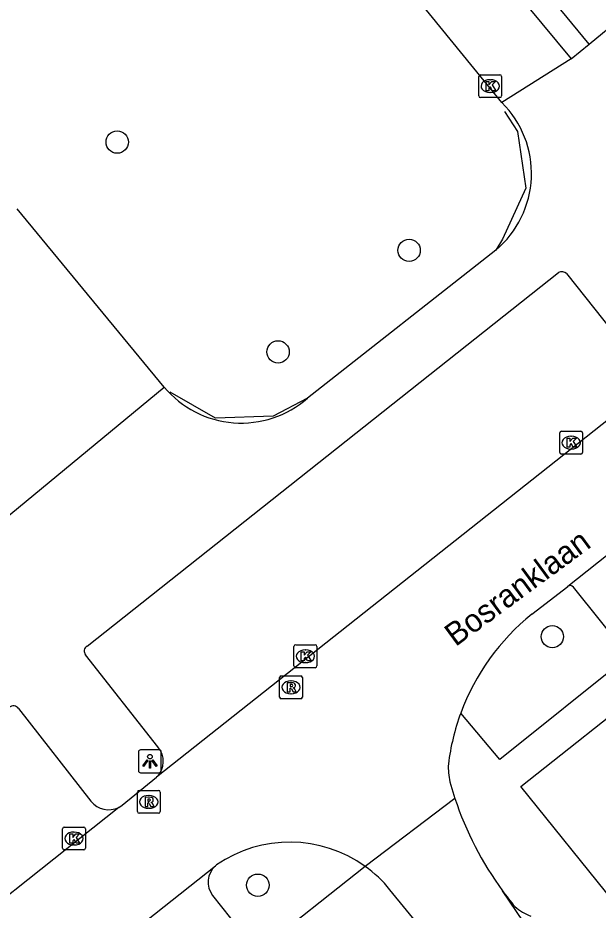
# Model space of a CAD drawing. Extents: x 162347 to 162868, y 381221 to 381813.
# Drawn here: x 162493.66 to 162519.02, y 381680.03 to 381719.03 of the extents above; entities that cross this region are included whole.
import ezdxf

# ---------------------------------------------------------------- set-up
doc = ezdxf.new("R2010")
doc.units = 0
for name, color, linetype in [('IMGEO_Boom', 7, 'Continuous'), ('IMGEO_Hek', 7, 'Continuous'), ('IMGEO_Kolk', 7, 'Continuous'), ('IMGEO_Lichtpunt', 7, 'Continuous'), ('IMGEO_Openbare_ruimte_label', 7, 'Continuous'), ('IMGEO_Pand', 7, 'Continuous'), ('IMGEO_Parkeervlak_open', 7, 'Continuous'), ('IMGEO_Rijbaan_lokaal_open', 7, 'Continuous'), ('IMGEO_Rioolput', 7, 'Continuous'), ('IMGEO_Voetpad_open', 7, 'Continuous')]:
    doc.layers.add(name, color=color, linetype=linetype)

msp = doc.modelspace()

# ---------------------------------------------------------------- linework, layer by layer
at = {"layer": 'IMGEO_Boom'}
for centre in [(162498.003, 381713.603), (162510.758, 381708.87), (162505.033, 381704.43), (162517.017, 381691.986), (162504.148, 381681.124)]:
    msp.add_circle(centre, 0.489, dxfattribs=at)
at = {"layer": 'IMGEO_Hek'}
for points in [[(162514.929, 381714.942), (162515.499, 381714.058), (162515.859, 381711.59), (162514.835, 381709.353), (162514.55, 381708.882)], [(162514.55, 381708.882), (162506.322, 381702.406)], [(162506.322, 381702.406), (162504.816, 381701.628), (162502.292, 381701.534), (162500.316, 381702.673)]]:
    msp.add_lwpolyline(points, dxfattribs=at)
at = {"layer": 'IMGEO_Kolk'}
for p, q in [((162513.802, 381715.621), (162513.802, 381716.473)), ((162513.877, 381716.547), (162514.729, 381716.547)), ((162514.803, 381716.473), (162514.803, 381715.621)), ((162514.29, 381716.327), (162514.315, 381716.327)), ((162514.313, 381715.767), (162514.288, 381715.767)), ((162514.729, 381715.547), (162513.877, 381715.547)), ((162517.34, 381700.036), (162517.34, 381700.888)), ((162517.415, 381700.962), (162518.267, 381700.962)), ((162518.341, 381700.888), (162518.341, 381700.036)), ((162517.828, 381700.742), (162517.853, 381700.742)), ((162517.851, 381700.182), (162517.826, 381700.182)), ((162518.267, 381699.962), (162517.415, 381699.962)), ((162505.727, 381690.704), (162505.727, 381691.556)), ((162505.802, 381691.63), (162506.654, 381691.63)), ((162506.728, 381691.556), (162506.728, 381690.704)), ((162506.215, 381691.41), (162506.24, 381691.41)), ((162506.238, 381690.85), (162506.213, 381690.85)), ((162506.654, 381690.63), (162505.802, 381690.63)), ((162495.615, 381682.738), (162495.615, 381683.59)), ((162495.69, 381683.664), (162496.542, 381683.664)), ((162496.103, 381683.444), (162496.128, 381683.444)), ((162496.616, 381683.59), (162496.616, 381682.738)), ((162496.542, 381682.664), (162495.69, 381682.664)), ((162496.126, 381682.884), (162496.101, 381682.884))]:
    msp.add_line(p, q, dxfattribs=at)
for points in [[(162513.802, 381715.621), (162513.802, 381716.473)], [(162513.877, 381716.547), (162514.729, 381716.547)], [(162514.803, 381716.473), (162514.803, 381715.621)], [(162514.123, 381716.247), (162514.246, 381716.247), (162514.246, 381716.096), (162514.376, 381716.247), (162514.54, 381716.247), (162514.394, 381716.096), (162514.547, 381715.847), (162514.395, 381715.847), (162514.31, 381716.011), (162514.246, 381715.944), (162514.246, 381715.847), (162514.123, 381715.847), (162514.123, 381716.247)], [(162514.729, 381715.547), (162513.877, 381715.547)], [(162517.34, 381700.036), (162517.34, 381700.888)], [(162517.415, 381700.962), (162518.267, 381700.962)], [(162518.341, 381700.888), (162518.341, 381700.036)], [(162517.661, 381700.662), (162517.784, 381700.662), (162517.784, 381700.511), (162517.914, 381700.662), (162518.078, 381700.662), (162517.932, 381700.511), (162518.085, 381700.262), (162517.933, 381700.262), (162517.848, 381700.426), (162517.784, 381700.359), (162517.784, 381700.262), (162517.661, 381700.262), (162517.661, 381700.662)], [(162518.267, 381699.962), (162517.415, 381699.962)], [(162505.727, 381690.704), (162505.727, 381691.556)], [(162505.802, 381691.63), (162506.654, 381691.63)], [(162506.728, 381691.556), (162506.728, 381690.704)], [(162506.048, 381691.33), (162506.171, 381691.33), (162506.171, 381691.179), (162506.301, 381691.33), (162506.465, 381691.33), (162506.319, 381691.179), (162506.472, 381690.93), (162506.32, 381690.93), (162506.235, 381691.094), (162506.171, 381691.027), (162506.171, 381690.93), (162506.048, 381690.93), (162506.048, 381691.33)], [(162506.654, 381690.63), (162505.802, 381690.63)], [(162495.615, 381682.738), (162495.615, 381683.59)], [(162495.69, 381683.664), (162496.542, 381683.664)], [(162495.936, 381683.364), (162496.059, 381683.364), (162496.059, 381683.213), (162496.189, 381683.364), (162496.353, 381683.364), (162496.207, 381683.213), (162496.36, 381682.964), (162496.208, 381682.964), (162496.123, 381683.128), (162496.059, 381683.061), (162496.059, 381682.964), (162495.936, 381682.964), (162495.936, 381683.364)], [(162496.616, 381683.59), (162496.616, 381682.738)], [(162496.542, 381682.664), (162495.69, 381682.664)]]:
    msp.add_lwpolyline(points, dxfattribs=at)
for centre, start, end in [((162513.879, 381716.471), 91.552, 178.448), ((162513.879, 381716.471), 91.552, 178.448), ((162514.727, 381716.471), 1.552, 88.448), ((162514.727, 381716.471), 1.552, 88.448), ((162513.879, 381715.623), 181.552, 268.448), ((162513.879, 381715.623), 181.552, 268.448), ((162514.727, 381715.623), 271.552, 358.448), ((162514.727, 381715.623), 271.552, 358.448), ((162517.417, 381700.886), 91.552, 178.448), ((162517.417, 381700.886), 91.552, 178.448), ((162518.265, 381700.886), 1.552, 88.448), ((162518.265, 381700.886), 1.552, 88.448), ((162517.417, 381700.038), 181.552, 268.448), ((162517.417, 381700.038), 181.552, 268.448), ((162518.265, 381700.038), 271.552, 358.448), ((162518.265, 381700.038), 271.552, 358.448), ((162505.804, 381691.554), 91.552, 178.448), ((162505.804, 381691.554), 91.552, 178.448), ((162506.652, 381691.554), 1.552, 88.448), ((162506.652, 381691.554), 1.552, 88.448), ((162505.804, 381690.706), 181.552, 268.448), ((162505.804, 381690.706), 181.552, 268.448), ((162506.652, 381690.706), 271.552, 358.448), ((162506.652, 381690.706), 271.552, 358.448), ((162495.692, 381683.588), 91.552, 178.448), ((162495.692, 381683.588), 91.552, 178.448), ((162496.54, 381683.588), 1.552, 88.448), ((162496.54, 381683.588), 1.552, 88.448), ((162495.692, 381682.74), 181.552, 268.448), ((162495.692, 381682.74), 181.552, 268.448), ((162496.54, 381682.74), 271.552, 358.448), ((162496.54, 381682.74), 271.552, 358.448)]:
    msp.add_arc(centre, 0.0765, start, end, dxfattribs=at)
for centre, major_axis, ratio, start_param, end_param in [((162514.289, 381716.047), (-0.387, 0.002), 0.722429, 4.712389, 7.853982), ((162514.314, 381716.047), (-0.39, 0.002), 0.717154, 1.570796, 4.712389), ((162517.827, 381700.462), (-0.387, 0.002), 0.722429, 4.712389, 7.853982), ((162517.852, 381700.462), (-0.39, 0.002), 0.717154, 1.570796, 4.712389), ((162506.214, 381691.13), (-0.387, 0.002), 0.722429, 4.712389, 7.853982), ((162506.239, 381691.13), (-0.39, 0.002), 0.717154, 1.570796, 4.712389), ((162496.102, 381683.164), (-0.387, 0.002), 0.722429, 4.712389, 7.853982), ((162496.127, 381683.164), (-0.39, 0.002), 0.717154, 1.570796, 4.712389)]:
    msp.add_ellipse(centre, major_axis=major_axis, ratio=ratio, start_param=start_param, end_param=end_param, dxfattribs=at)
at = {"layer": 'IMGEO_Lichtpunt'}
for p, q in [((162498.934, 381686.942), (162498.934, 381686.135)), ((162498.934, 381686.942), (162498.934, 381686.135)), ((162499.836, 381687.037), (162499.028, 381687.037)), ((162499.836, 381687.037), (162499.028, 381687.037)), ((162499.93, 381686.135), (162499.93, 381686.942)), ((162499.93, 381686.135), (162499.93, 381686.942)), ((162499.028, 381686.041), (162499.836, 381686.041)), ((162499.028, 381686.041), (162499.836, 381686.041))]:
    msp.add_line(p, q, dxfattribs=at)
for points in [[(162499.308, 381686.606), (162499.347, 381686.578), (162499.159, 381686.316), (162499.121, 381686.343), (162499.308, 381686.606)], [(162499.41, 381686.558), (162499.457, 381686.558), (162499.457, 381686.236), (162499.41, 381686.236), (162499.41, 381686.558)], [(162499.52, 381686.578), (162499.558, 381686.605), (162499.745, 381686.343), (162499.706, 381686.315), (162499.52, 381686.578)]]:
    msp.add_lwpolyline(points, dxfattribs=at)
msp.add_circle((162499.433, 381686.74), 0.0994, dxfattribs=at)
for centre, start, end in [((162499.028, 381686.942), 90, 180), ((162499.028, 381686.942), 90, 180), ((162499.836, 381686.942), 0, 90), ((162499.836, 381686.942), 0, 90), ((162499.028, 381686.135), 180, 270), ((162499.028, 381686.135), 180, 270), ((162499.836, 381686.135), 270, 0), ((162499.836, 381686.135), 270, 360)]:
    msp.add_arc(centre, 0.0946, start, end, dxfattribs=at)
at = {"layer": 'IMGEO_Pand'}
for points in [[(162518.63, 381717.886), (162525.696, 381723.717)], [(162518.63, 381717.886), (162514.15, 381723.315)], [(162500.056, 381702.892), (162493.628, 381710.68)], [(162493.014, 381697.083), (162500.056, 381702.892)]]:
    msp.add_lwpolyline(points, dxfattribs=at)
at = {"layer": 'IMGEO_Parkeervlak_open'}
for points in [[(162520.357, 381691.127), (162517.937, 381694.149)], [(162502.172, 381680.676), (162502.959, 381679.681), (162503.867, 381678.548)]]:
    msp.add_lwpolyline(points, dxfattribs=at)
for centre, radius, start, end in [((162517.8, 381694.047), 0.171, 36.6189, 125.6345), ((162502.928, 381681.257), 0.953, 131.4651, 217.5081)]:
    msp.add_arc(centre, radius, start, end, dxfattribs=at)
at = {"layer": 'IMGEO_Rijbaan_lokaal_open'}
for points in [[(162517.7, 381694.186), (162533.842, 381706.991)], [(162522.199, 381703.639), (162499.727, 381685.849)], [(162516.127, 381692.971), (162517.688, 381694.176), (162517.7, 381694.186)], [(162498.069, 381684.526), (162498.226, 381684.626), (162499.727, 381685.849)], [(162512.542, 381685.64), (162512.763, 381684.914)], [(162512.763, 381684.914), (162508.84, 381681.944)], [(162498.069, 381684.526), (162479.74, 381669.953)], [(162479.911, 381664.241), (162502.297, 381681.971)], [(162502.344, 381682.01), (162502.297, 381681.971)], [(162550.263, 381630.982), (162546.437, 381635.708), (162536.447, 381648.07), (162524.281, 381663.125), (162512.103, 381678.261), (162509.921, 381680.927)], [(162518.207, 381675.915), (162514.84, 381680.884)]]:
    msp.add_lwpolyline(points, dxfattribs=at)
for centre, radius, start, end in [((162522.382, 381685.193), 9.981, 128.8048, 159.7775), ((162522.376, 381685.192), 9.976, 159.7597, 172.9213), ((162515.116, 381686.251), 2.645, 176.3103, 193.3506), ((162526.741, 381689.568), 14.733, 198.4147, 216.1171), ((162505.545, 381677.353), 5.651, 54.332, 124.5038), ((162505.532, 381677.345), 5.666, 39.221, 54.2736)]:
    msp.add_arc(centre, radius, start, end, dxfattribs=at)
at = {"layer": 'IMGEO_Rioolput'}
for p, q in [((162505.098, 381689.345), (162505.098, 381690.197)), ((162505.173, 381690.271), (162506.025, 381690.271)), ((162505.586, 381690.051), (162505.611, 381690.051)), ((162506.099, 381690.197), (162506.099, 381689.345)), ((162506.025, 381689.271), (162505.173, 381689.271)), ((162505.609, 381689.491), (162505.584, 381689.491)), ((162498.959, 381685.265), (162499.811, 381685.265)), ((162498.884, 381684.339), (162498.884, 381685.191)), ((162499.372, 381685.045), (162499.397, 381685.045)), ((162499.885, 381685.191), (162499.885, 381684.339)), ((162499.395, 381684.485), (162499.37, 381684.485)), ((162499.811, 381684.265), (162498.959, 381684.265))]:
    msp.add_line(p, q, dxfattribs=at)
for points in [[(162505.098, 381689.345), (162505.098, 381690.197)], [(162505.173, 381690.271), (162506.025, 381690.271)], [(162505.687, 381689.969), (162505.435, 381689.971), (162505.435, 381689.571)], [(162506.099, 381690.197), (162506.099, 381689.345)], [(162505.435, 381689.571), (162505.559, 381689.571), (162505.559, 381689.733), (162505.57, 381689.733)], [(162505.613, 381689.89), (162505.559, 381689.89), (162505.559, 381689.809)], [(162505.559, 381689.809), (162505.611, 381689.809)], [(162505.617, 381689.704), (162505.688, 381689.571), (162505.828, 381689.571), (162505.763, 381689.697)], [(162506.025, 381689.271), (162505.173, 381689.271)], [(162498.959, 381685.265), (162499.811, 381685.265)], [(162498.884, 381684.339), (162498.884, 381685.191)], [(162499.473, 381684.963), (162499.221, 381684.965), (162499.221, 381684.565)], [(162499.399, 381684.884), (162499.345, 381684.884), (162499.345, 381684.803)], [(162499.885, 381685.191), (162499.885, 381684.339)], [(162499.221, 381684.565), (162499.345, 381684.565), (162499.345, 381684.727), (162499.356, 381684.727)], [(162499.345, 381684.803), (162499.397, 381684.803)], [(162499.403, 381684.698), (162499.474, 381684.565), (162499.614, 381684.565), (162499.549, 381684.691)], [(162499.811, 381684.265), (162498.959, 381684.265)]]:
    msp.add_lwpolyline(points, dxfattribs=at)
for centre, radius, start, end in [((162505.175, 381690.195), 0.0765, 91.552, 178.448), ((162505.175, 381690.195), 0.0765, 91.552, 178.448), ((162505.686, 381689.859), 0.109, 350.3612, 89.416), ((162506.023, 381690.195), 0.0765, 1.552, 88.448), ((162506.023, 381690.195), 0.0765, 1.552, 88.448), ((162505.569, 381689.68), 0.0533, 26.0293, 88.6989), ((162505.595, 381689.998), 0.19, 274.7715, 282.9687), ((162505.619, 381689.794), 0.0964, 77.0061, 93.1865), ((162505.633, 381689.851), 0.0378, 276.6634, 79.6772), ((162505.684, 381689.859), 0.112, 277.5842, 350.9817), ((162505.668, 381689.644), 0.108, 29.5134, 73.7905), ((162505.175, 381689.347), 0.0765, 181.552, 268.448), ((162505.175, 381689.347), 0.0765, 181.552, 268.448), ((162506.023, 381689.347), 0.0765, 271.552, 358.448), ((162506.023, 381689.347), 0.0765, 271.552, 358.448), ((162498.961, 381685.189), 0.0765, 91.552, 178.448), ((162498.961, 381685.189), 0.0765, 91.552, 178.448), ((162499.809, 381685.189), 0.0765, 1.552, 88.448), ((162499.809, 381685.189), 0.0765, 1.552, 88.448), ((162499.405, 381684.788), 0.0964, 77.0061, 93.1865), ((162499.419, 381684.845), 0.0378, 276.6634, 79.6772), ((162499.472, 381684.853), 0.109, 350.3612, 89.416), ((162499.355, 381684.674), 0.0533, 26.0293, 88.6989), ((162499.381, 381684.992), 0.19, 274.7715, 282.9687), ((162499.47, 381684.853), 0.112, 277.5842, 350.9817), ((162499.454, 381684.638), 0.108, 29.5134, 73.7905), ((162498.961, 381684.341), 0.0765, 181.552, 268.448), ((162498.961, 381684.341), 0.0765, 181.552, 268.448), ((162499.809, 381684.341), 0.0765, 271.552, 358.448), ((162499.809, 381684.341), 0.0765, 271.552, 358.448)]:
    msp.add_arc(centre, radius, start, end, dxfattribs=at)
for centre, major_axis, ratio, start_param, end_param in [((162505.585, 381689.771), (-0.387, 0.002), 0.722429, 4.712389, 7.853982), ((162505.61, 381689.771), (-0.39, 0.002), 0.717154, 1.570796, 4.712389), ((162499.371, 381684.765), (-0.387, 0.002), 0.722429, 4.712389, 7.853982), ((162499.396, 381684.765), (-0.39, 0.002), 0.717154, 1.570796, 4.712389)]:
    msp.add_ellipse(centre, major_axis=major_axis, ratio=ratio, start_param=start_param, end_param=end_param, dxfattribs=at)
at = {"layer": 'IMGEO_Voetpad_open'}
for points in [[(162513.359, 381722.662), (162517.837, 381717.246)], [(162514.818, 381715.325), (162510.426, 381720.718)], [(162517.837, 381717.246), (162518.63, 381717.886)], [(162517.837, 381717.246), (162514.818, 381715.325)], [(162514.55, 381708.882), (162506.322, 381702.406)], [(162496.692, 381691.57), (162517.292, 381707.897)], [(162517.644, 381707.854), (162520.842, 381703.818)], [(162499.778, 381687.175), (162496.621, 381691.19)], [(162520.357, 381691.127), (162514.723, 381686.61), (162513.016, 381688.643)], [(162525.341, 381684.847), (162520.82, 381681.267), (162519.71, 381680.397), (162515.643, 381685.433), (162521.312, 381689.925)], [(162493.695, 381688.84), (162496.858, 381684.792)], [(162508.84, 381681.944), (162504.138, 381678.21)]]:
    msp.add_lwpolyline(points, dxfattribs=at)
for centre, radius, start, end in [((162511.737, 381712.226), 4.37, 310.0727, 45.1636), ((162517.436, 381707.617), 0.315, 48.7401, 117.3305), ((162503.427, 381705.724), 4.403, 220.0268, 311.103), ((162496.805, 381691.352), 0.245, 117.3341, 221.4994), ((162493.46, 381688.668), 0.291, 36.2175, 129.7), ((162499.051, 381686.539), 0.966, 314.4181, 41.1767), ((162497.625, 381685.395), 0.976, 218.1731, 297.05), ((162527.152, 381689.885), 15.251, 216.1692, 219.4898), ((162516.925, 381681.989), 2.373, 229.4521, 248.9144)]:
    msp.add_arc(centre, radius, start, end, dxfattribs=at)

# ---------------------------------------------------------------- texts
at = {"layer": 'IMGEO_Openbare_ruimte_label'}
msp.add_text('Bosranklaan', height=1, rotation=36.3771, dxfattribs=at).set_placement((162512.788, 381691.526))

doc.saveas('drawing.dxf')
